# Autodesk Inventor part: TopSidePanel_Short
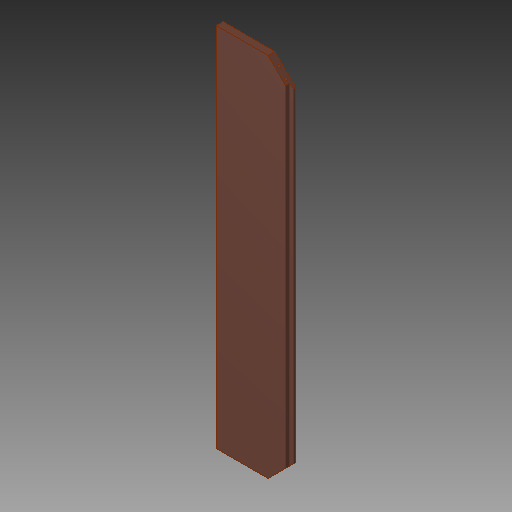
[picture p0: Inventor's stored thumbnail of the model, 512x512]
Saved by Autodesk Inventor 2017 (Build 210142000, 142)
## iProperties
Created: 2017-05
Part Number: TopSidePanel_Short
Material: Generic
Document SubType Name: Modeling
Designer: Savy
Density: 1 g/cm^3
Appearance: Default
Mass: 1089.31 g
Surface Area: 1970.89 cm^2
Volume: 1089.31 cm^3
Author: Savy
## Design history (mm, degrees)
feature "SOLID1"
body "Solid1"
